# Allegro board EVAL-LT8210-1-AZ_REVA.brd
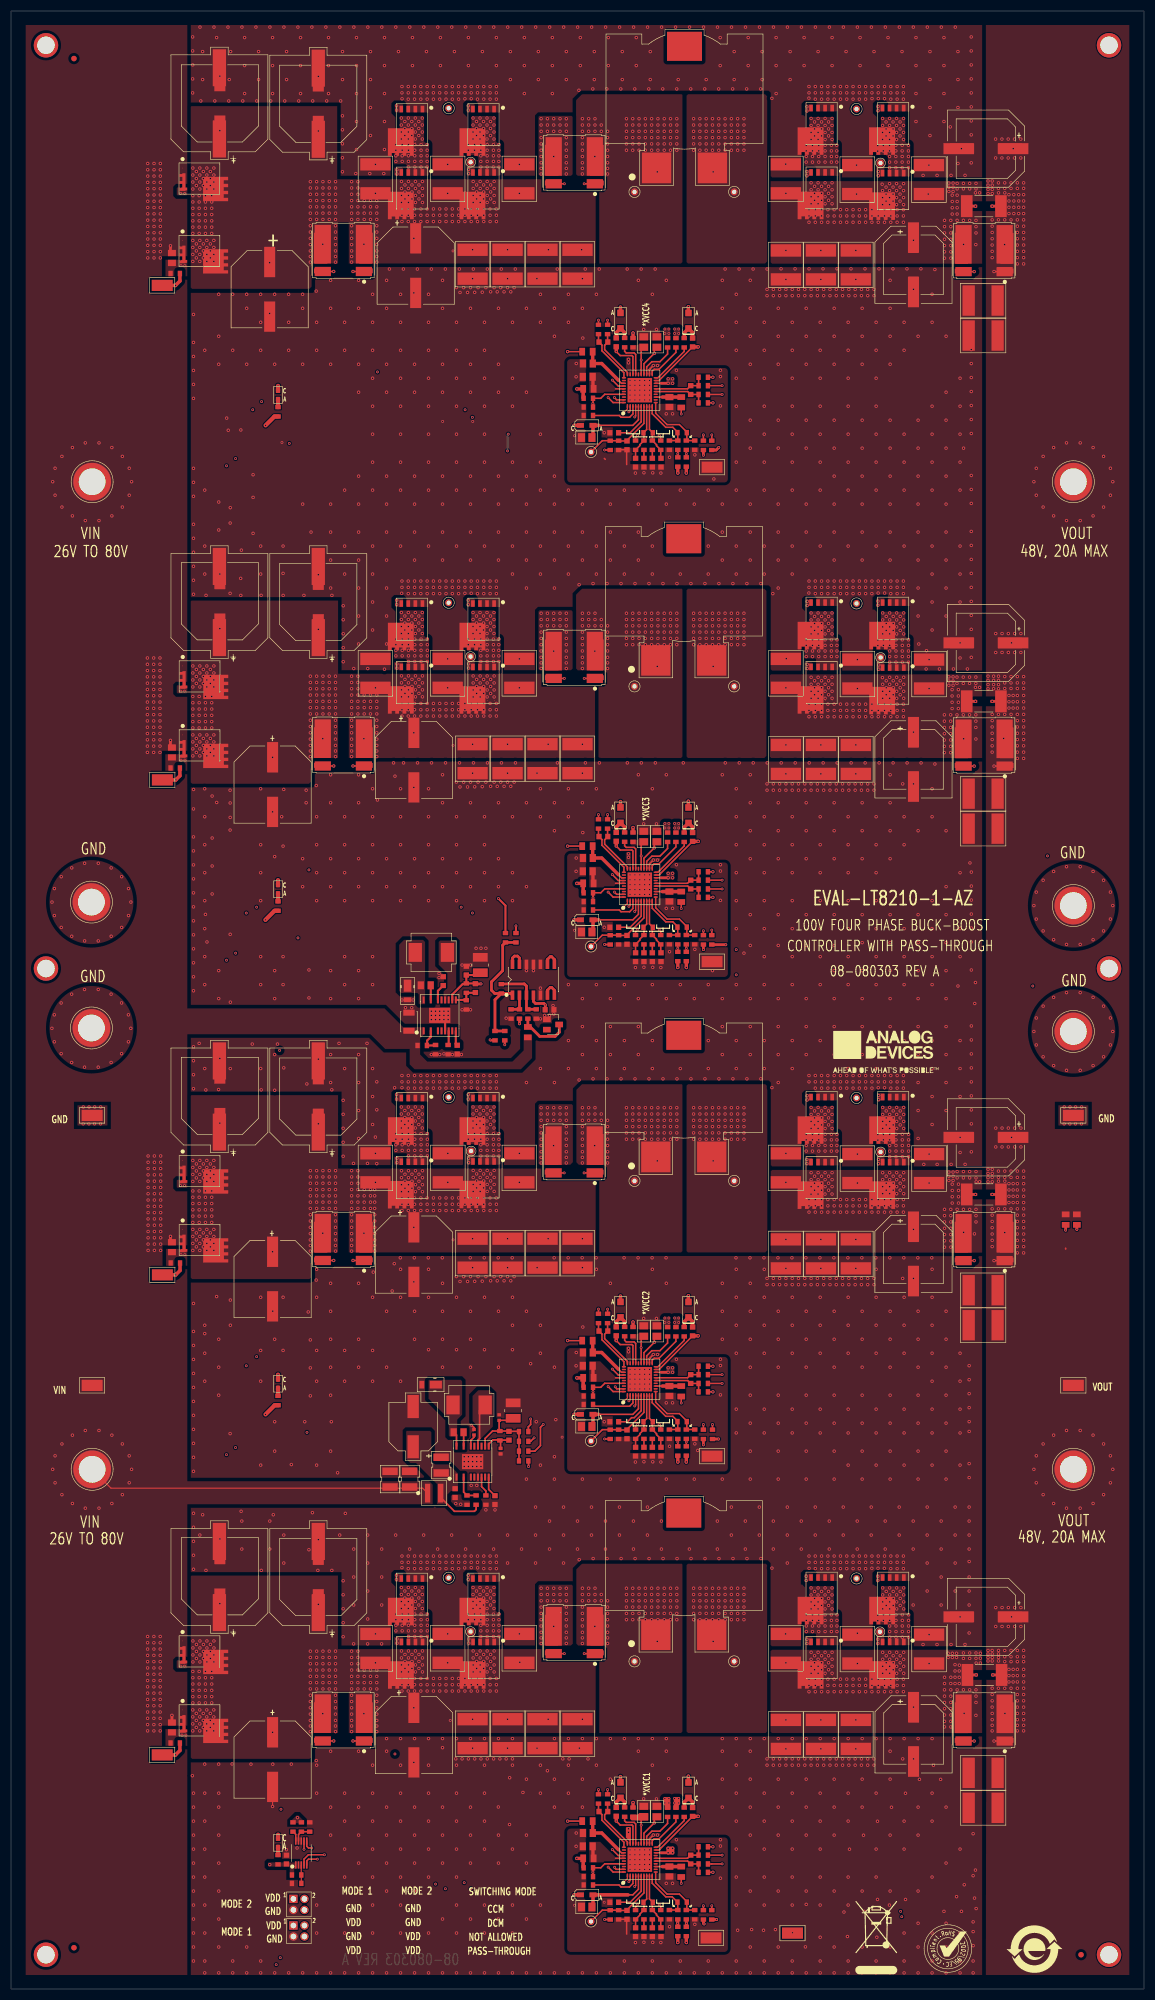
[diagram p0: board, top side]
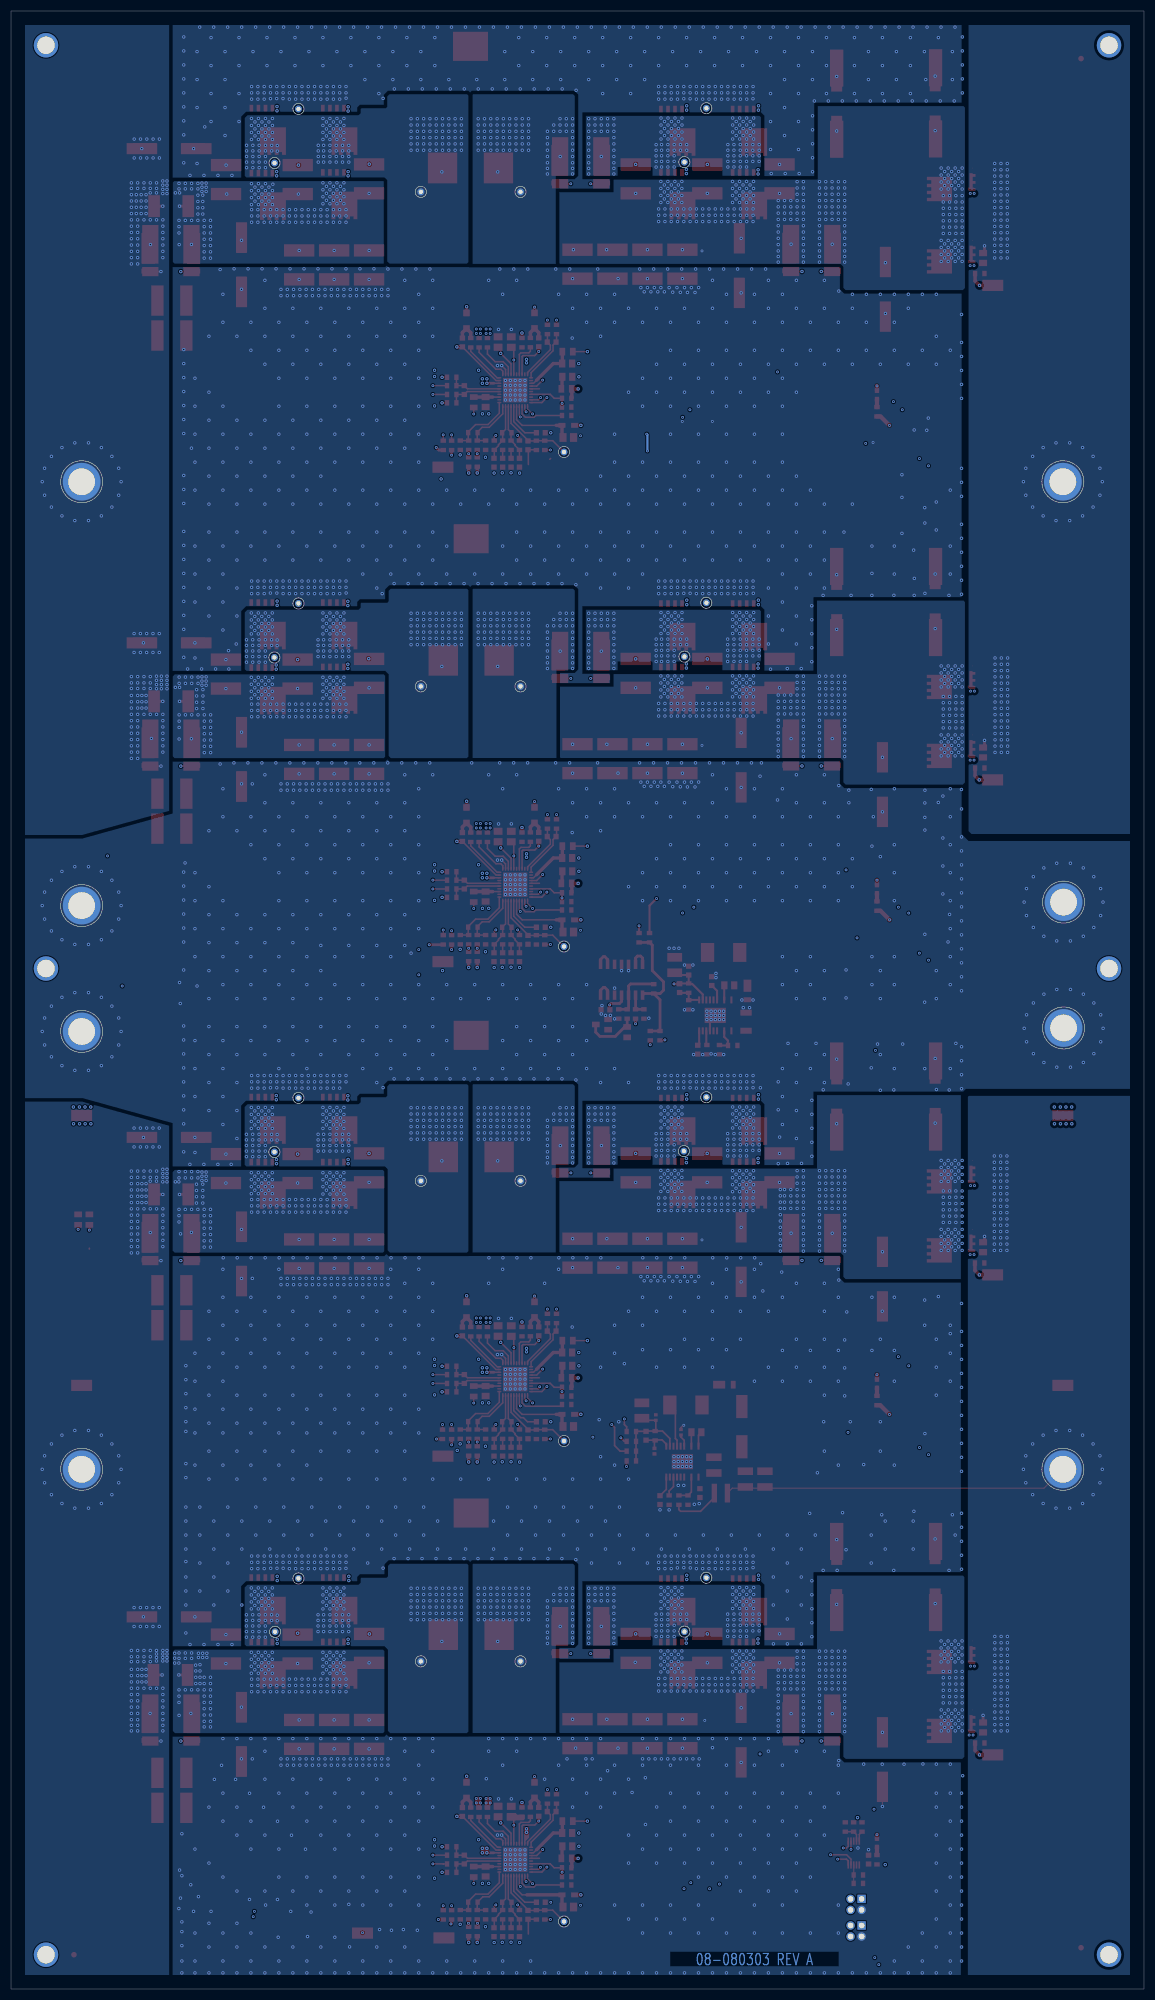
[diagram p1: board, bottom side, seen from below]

Outline 205.74 x 359.16 mm; copper layers: TOP, L2_GND, L3_SIG, L4_GND, L5_VCC, BOTTOM. Coordinates in mm from the lower left corner of the outline.
Outline path: 0,359.16 0,0 205.74,0 205.74,359.16 0,359.16

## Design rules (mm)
constraint set DEFAULT: min track width 0.203

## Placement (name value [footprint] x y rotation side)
C1  1UF  [C0805H55]  29.22 47.49 90 top
C2  68UF  [CPLSMSQ531H551]  47.5 41.66 270 top
C3  68UF  [CPLSMSQ531H551]  55.8 74.8 90 top
C3_1  68UF  [CPLSMSQ673H886]  55.8 74.8 90 top
C4  68UF  [CPLSMSQ531H551]  37.92 74.93 90 top
C4_1  68UF  [CPLSMSQ673H886]  37.85 74.8 90 top
C5  1UF  [C0805H55]  104.72 25.91 0 top
C6  1UF  [C0805H55]  104.75 28.32 0 top
C7  68UF  [CPLSMSQ531H551]  73.15 46.1 270 top
C8  33UF  [CSML236W200H272]  66.18 61.85 270 top
C9  33UF  [CSML236W200H272]  79.3 61.85 270 top
C10  33UF  [CSML236W200H272]  92.3 61.85 270 top
C11  33UF  [CSML236W200H272]  83.82 46.35 90 top
C12  33UF  [CSML236W200H272]  90.17 46.35 90 top
C13  33UF  [CSML236W200H272]  96.52 46.35 90 top
C14  33UF  [CSML236W200H272]  102.87 46.35 90 top
C15  1000pF  [C0603]  107.57 32.22 0 top
C16  33UF  [CSML236W200H272]  140.72 61.85 270 top
C17  33UF  [CSML236W200H272]  153.7 61.72 270 top
C18  33UF  [CSML236W200H272]  166.71 61.72 270 top
C19  33UF  [CSML236W200H272]  140.72 46.23 90 top
C20  33UF  [CSML236W200H272]  147.07 46.23 90 top
C21  33UF  [CSML236W200H272]  153.42 46.23 90 top
C22  100UF  [CPLSMSQ406H500]  163.89 46.23 270 top
C22_1  68UF  [CPLSMSQ531H551]  163.89 46.23 270 top
C23  100UF  [CPLSMSQ406H500]  177.04 67.56 180 top
C23_1  68UF  [CPLSMSQ531H551]  177.04 67.56 180 top
C24  0.1uF  [C0603]  123.42 23.5 270 top
C25  1UF  [C0805H55]  29.22 134.7 90 top
C26  68UF  [CPLSMSQ531H551]  47.5 128.9 270 top
C27  68UF  [CPLSMSQ531H551]  55.8 162.05 90 top
C27_1  68UF  [CPLSMSQ673H886]  55.8 162.05 90 top
C28  68UF  [CPLSMSQ531H551]  37.92 162.18 90 top
C28_1  68UF  [CPLSMSQ673H886]  37.85 162.05 90 top
C29  1UF  [C0805H55]  104.72 113.16 0 top
C30  1UF  [C0805H55]  104.75 115.57 0 top
C31  68UF  [CPLSMSQ531H551]  73.15 133.35 270 top
C32  33UF  [CSML236W200H272]  66.18 149.1 270 top
C33  33UF  [CSML236W200H272]  79.32 149.1 270 top
C34  33UF  [CSML236W200H272]  92.3 149.1 270 top
C35  33UF  [CSML236W200H272]  83.82 133.6 90 top
C36  33UF  [CSML236W200H272]  90.17 133.6 90 top
C37  33UF  [CSML236W200H272]  96.52 133.6 90 top
C38  33UF  [CSML236W200H272]  102.87 133.6 90 top
C39  1000pF  [C0603]  107.57 119.47 0 top
C40  33UF  [CSML236W200H272]  140.72 149.1 270 top
C41  33UF  [CSML236W200H272]  153.7 148.97 270 top
C42  33UF  [CSML236W200H272]  166.71 148.97 270 top
C43  33UF  [CSML236W200H272]  140.72 133.48 90 top
C44  33UF  [CSML236W200H272]  147.07 133.48 90 top
C45  33UF  [CSML236W200H272]  153.42 133.48 90 top
C46  100UF  [CPLSMSQ406H500]  163.88 133.48 270 top
C46_1  68UF  [CPLSMSQ531H551]  163.88 133.48 270 top
C47  100UF  [CPLSMSQ406H500]  177.04 154.63 180 top
C47_1  68UF  [CPLSMSQ531H551]  177.04 154.63 180 top
C48  0.1uF  [C0603]  123.42 110.75 270 top
C49  1UF  [C0805H55]  29.22 224.52 90 top
C50  68UF  [CPLSMSQ531H551]  47.5 218.69 270 top
C51  68UF  [CPLSMSQ531H551]  55.8 251.84 90 top
C51_1  68UF  [CPLSMSQ673H886]  55.8 251.84 90 top
C52  68UF  [CPLSMSQ531H551]  37.92 251.97 90 top
C52_1  68UF  [CPLSMSQ673H886]  37.85 251.84 90 top
C53  1UF  [C0805H55]  104.72 202.95 0 top
C54  1UF  [C0805H55]  104.75 205.36 0 top
C55  68UF  [CPLSMSQ531H551]  73.15 223.14 270 top
C56  33UF  [CSML236W200H272]  66.18 238.89 270 top
C57  33UF  [CSML236W200H272]  79.3 238.89 270 top
C58  33UF  [CSML236W200H272]  92.3 238.89 270 top
C59  33UF  [CSML236W200H272]  83.82 223.39 90 top
C60  33UF  [CSML236W200H272]  90.17 223.39 90 top
C61  33UF  [CSML236W200H272]  96.52 223.39 90 top
C62  33UF  [CSML236W200H272]  102.87 223.39 90 top
C63  1000pF  [C0603]  107.57 209.26 0 top
C64  33UF  [CSML236W200H272]  140.72 238.89 270 top
C65  33UF  [CSML236W200H272]  153.7 238.76 270 top
C66  33UF  [CSML236W200H272]  166.71 238.76 270 top
C67  33UF  [CSML236W200H272]  140.72 223.27 90 top
C68  33UF  [CSML236W200H272]  153.42 223.27 90 top
C69  33UF  [CSML236W200H272]  147.07 223.27 90 top
C70  100UF  [CPLSMSQ406H500]  163.88 223.27 270 top
C70_1  68UF  [CPLSMSQ531H551]  163.88 223.27 270 top
C71  100UF  [CPLSMSQ406H500]  177.04 244.42 180 top
C71_1  68UF  [CPLSMSQ531H551]  177.04 244.42 180 top
C72  0.1uF  [C0603]  123.42 200.54 270 top
C73  1UF  [C0805H55]  29.22 314.31 90 top
C74  68UF  [CPLSMSQ531H551]  46.96 308.62 270 top
C75  68UF  [CPLSMSQ531H551]  55.8 342.33 90 top
C75_1  68UF  [CPLSMSQ673H886]  55.8 342.33 90 top
C76  68UF  [CPLSMSQ531H551]  37.92 342.38 90 top
C76_1  68UF  [CPLSMSQ673H886]  37.85 342.39 90 top
C77  1UF  [C0805H55]  104.72 292.73 0 top
C78  1UF  [C0805H55]  104.75 295.15 0 top
C79  68UF  [CPLSMSQ531H551]  73.48 312.93 270 top
C80  33UF  [CSML236W200H272]  66.18 328.68 270 top
C81  33UF  [CSML236W200H272]  79.3 328.68 270 top
C82  33UF  [CSML236W200H272]  92.3 328.68 270 top
C83  33UF  [CSML236W200H272]  83.82 313.18 90 top
C84  33UF  [CSML236W200H272]  90.17 313.18 90 top
C85  33UF  [CSML236W200H272]  96.52 313.18 90 top
C86  33UF  [CSML236W200H272]  102.87 313.18 90 top
C87  1000pF  [C0603]  107.57 299.04 0 top
C88  33UF  [CSML236W200H272]  140.72 328.68 270 top
C89  33UF  [CSML236W200H272]  153.67 328.55 270 top
C90  33UF  [CSML236W200H272]  166.69 328.55 270 top
C91  33UF  [CSML236W200H272]  140.72 313.05 90 top
C92  33UF  [CSML236W200H272]  147.07 313.05 90 top
C93  33UF  [CSML236W200H272]  153.42 313.05 90 top
C94  100UF  [CPLSMSQ406H500]  163.88 313.08 270 top
C94_1  68UF  [CPLSMSQ531H551]  163.88 313.08 270 top
C95  100UF  [CPLSMSQ406H500]  177.04 334.16 180 top
C95_1  68UF  [CPLSMSQ531H551]  177.04 334.16 180 top
C96  0.1uF  [C0603]  123.42 290.33 270 top
C97  0.1uF  [C0603]  50.01 23.49 90 top
C98  10uF  [CPLSMSQ327H413]  73.02 102.11 90 top
C99  2.2UF  [C1210H110]  72.39 92.58 90 top
C100  2.2UF  [C1210H110]  78.1 95.12 90 top
C101  2.2UF  [C1210H110]  68.83 92.58 90 top
C102  TBD0603  [C0603]  80.64 90.04 90 top
C103  0.1uF  [C0603]  87.88 88.77 270 top
C104  0.1UF  [C0805]  81.28 101.09 0 top
C105  4.7PF  [C0603]  90.42 100.46 270 top
C106  2.2UF  [C0402]  84.07 101.09 90 top
C107  47uF  [C1210-2]  91.19 105.03 90 top
C108  1uF  [C0402]  88.65 103.76 90 top
C109  33UF  [CSML236W200H272]  176.53 32.89 0 top
C110  33UF  [CSML236W200H272]  176.53 39.24 0 top
C111  33UF  [CSML236W200H272]  176.53 217.04 0 top
C112  33UF  [CSML236W200H272]  176.53 210.69 0 top
C113  33UF  [CSML236W200H272]  176.53 306.58 0 top
C114  33UF  [CSML236W200H272]  176.53 300.23 0 top
C115  33UF  [CSML236W200H272]  176.53 126.87 0 top
C116  33UF  [CSML236W200H272]  176.53 120.52 0 top
C117  10UF  [C1210H106]  72.26 175.64 90 top
C118  0.01uF  [C0603]  81.03 170.56 270 top
C119  0.1uF  [C0603]  97.79 177.8 0 top
C120  0.1UF  [C0805]  75.31 182.25 0 top
C121  4.7PF  [C0603]  84.33 181.74 270 top
C122  2.2UF  [C0603]  78.49 183.01 90 top
C123  47uF  [C1210-2]  85.22 185.93 90 top
C124  1uF  [C0603]  82.68 184.91 90 top
CBST1  0.1uF  [C0603]  109.91 32.17 90 top
CBST2  0.1uF  [C0603]  123.77 32.14 270 top
CBST3  0.1uF  [C0603]  109.91 119.42 90 top
CBST4  0.1uF  [C0603]  123.77 119.39 270 top
CBST5  0.1uF  [C0603]  109.91 209.21 90 top
CBST6  0.1uF  [C0603]  123.77 209.18 270 top
CBST7  0.1uF  [C0603]  109.91 298.99 90 top
CBST8  0.1uF  [C0603]  123.77 298.97 270 top
CC1  6800pF  [C0603]  114.93 10.31 90 top
CC2  6800pF  [C0603]  116.46 10.31 90 top
CC3  6800pF  [C0603]  114.94 97.56 90 top
CC4  6800pF  [C0603]  116.46 97.56 90 top
CC5  6800pF  [C0603]  114.93 187.35 90 top
CC6  6800pF  [C0603]  116.46 187.35 90 top
CC7  6800pF  [C0603]  114.93 277.14 90 top
CC8  6800pF  [C0603]  116.46 277.14 90 top
CFOUT1  1UF  [C0805H55]  119.56 21.33 270 top
CFOUT2  1UF  [C0805H55]  119.56 108.58 270 top
CFOUT3  1UF  [C0805H55]  119.56 198.37 270 top
CFOUT4  1UF  [C0805H55]  119.56 288.16 270 top
CGATE1  4.7uF  [C0805H53]  117.28 32.22 90 top
CGATE2  4.7uF  [C0805H53]  117.28 119.47 90 top
CGATE3  4.7uF  [C0805H53]  117.28 209.26 90 top
CGATE4  4.7uF  [C0805H53]  117.28 299.05 90 top
CIMON1  0.01uF  [C0603]  111.86 13.46 270 top
CIMON2  0.01uF  [C0603]  111.86 100.71 270 top
CIMON3  0.01uF  [C0603]  111.86 190.5 270 top
CIMON4  0.01uF  [C0603]  111.86 280.29 270 top
CP1  220pF  [C0603]  113.41 10.31 90 top
CP2  62PF  [C0603]  118.03 10.31 90 top
CP3  220pF  [C0603]  113.41 97.56 90 top
CP4  62PF  [C0603]  118.03 97.56 90 top
CP5  220pF  [C0603]  113.41 187.35 90 top
CP6  62PF  [C0603]  118.03 187.35 90 top
CP7  220pF  [C0603]  113.41 277.14 90 top
CP8  62PF  [C0603]  118.03 277.14 90 top
CSS1  0.22UF  [C0603]  109.54 15.75 0 top
CSS2  0.22UF  [C0603]  109.54 103 0 top
CSS3  0.22UF  [C0603]  109.54 192.79 0 top
CSS4  0.22UF  [C0603]  109.54 282.57 0 top
CVDD1  4.7uF  [C0805H53]  104.55 14.88 0 top
CVDD2  4.7uF  [C0805H53]  104.55 102.13 0 top
CVDD3  4.7uF  [C0805H53]  104.55 191.92 0 top
CVDD4  4.7uF  [C0805H53]  104.55 281.71 0 top
CXVCC1  4.7uF  [C0805H53]  114.9 32.22 270 top
CXVCC2  4.7uF  [C0805H53]  114.9 119.47 270 top
CXVCC3  4.7uF  [C0805H53]  114.9 209.26 270 top
CXVCC4  4.7uF  [C0805H53]  114.9 299.04 270 top
D1  PMEG3010BEA,115  [SOD323]  104.55 17.09 0 top
D2  BZX84-C18V  [SOT23]  98.42 175.13 270 top
D3  PMEG3010BEA,115  [SOD323]  104.55 104.34 0 top
D4  DFLS1100-7  [POWERDI123]  72.01 181.23 270 top
D5  PMEG3010BEA,115  [SOD323]  104.55 194.13 0 top
D7  PMEG3010BEA,115  [SOD323]  104.55 283.92 0 top
D9  DFLS1100-7  [POWERDI123]  76.2 109.73 180 top
DBST1  US1GWF-7  [SOD123F]  110.68 36.1 90 top
DBST2  US1GWF-7  [SOD123F]  123.03 36.09 90 top
DBST3  US1GWF-7  [SOD123F]  110.68 123.35 90 top
DBST4  US1GWF-7  [SOD123F]  123.03 123.34 90 top
DBST5  US1GWF-7  [SOD123F]  110.68 213.14 90 top
DBST6  US1GWF-7  [SOD123F]  123.03 213.13 90 top
DBST7  US1GWF-7  [SOD123F]  110.68 302.93 90 top
DBST8  US1GWF-7  [SOD123F]  123.03 302.92 90 top
DG1  5019  [CNKEY5019]  27.46 42.51 0 top
DG2  5019  [CNKEY5019]  27.48 129.67 0 top
DG3  5019  [CNKEY5019]  27.48 219.54 0 top
DG4  5019  [CNKEY5019]  27.46 309.33 0 top
DS1  HSMC-C197  [LED0603H12]  48.49 26.54 270 top
DS2  HSMC-C197  [LED0603H12]  48.49 109.91 270 top
DS3  HSMC-C197  [LED0603H12]  48.49 199.69 270 top
DS4  HSMC-C197  [LED0603H12]  48.49 289.45 270 top
E1  5019  [CNKEY5019]  14.73 109.6 0 top
E2  5019  [CNKEY5019]  14.73 158.62 0 top
E3  5019  [CNKEY5019]  192.91 158.62 0 top
E4  5019  [CNKEY5019]  192.91 109.6 0 top
GND1  5019  [CNKEY5019]  127.13 9.27 180 top
GND2  5019  [CNKEY5019]  127.31 96.75 180 top
GND3  5019  [CNKEY5019]  127.3 186.54 180 top
GND4  5019  [CNKEY5019]  127.3 276.33 180 top
IMON  5019  [CNKEY5019]  141.91 10.15 180 top
IMON1  TESTPAD  [TPC50D30]  105.32 12.26 270 top
IMON2  TESTPAD  [TPC50D30]  105.32 99.5 270 top
IMON3  TESTPAD  [TPC50D30]  105.32 189.29 270 top
IMON4  TESTPAD  [TPC50D30]  105.32 279.08 270 top
JP1  TMM-102-02-L-D  [CNTHMHDR2X2L157W155H225]  51.28 11.53 270 top
JP2  TMM-102-02-L-D  [CNTHMHDR2X2L157W155H225]  51.28 16.36 270 top
L1  15UH  [LSML1102W764H728]  122.17 75.91 0 top
L1A  TESTPAD  [TPC50D30]  113.22 59.49 0 top
L1B  TESTPAD  [TPC50D30]  131.32 59.49 0 top
L2  15UH  [LSML1102W764H728]  122.17 162.65 0 top
L2A  TESTPAD  [TPC50D30]  113.22 146.74 0 top
L2B  TESTPAD  [TPC50D30]  131.32 146.74 0 top
L3  15UH  [LSML1102W764H728]  122.17 252.82 0 top
L3A  TESTPAD  [TPC50D30]  113.22 236.52 0 top
L3B  TESTPAD  [TPC50D30]  131.32 236.52 0 top
L4  15UH  [LSML1102W764H728]  122.3 342.23 0 top
L4A  TESTPAD  [TPC50D30]  113.22 326.31 0 top
L4B  TESTPAD  [TPC50D30]  131.32 326.31 0 top
L5  2.2uH  [LSMSQ157H83_CC]  76.83 90.04 0 top
L6  22UH  [LSML270W255H118]  83.18 106.05 180 top
L7  22UH  [LSML270W255H118]  76.33 188.21 180 top
MA1  BSC070N10NS3GATMA1  [SON8]  72.81 60.19 180 top
MA2  BSC070N10NS3GATMA1  [SON8]  85.83 60.19 180 top
MA3  BSC070N10NS3GATMA1  [SON8]  72.78 147.38 180 top
MA4  BSC070N10NS3GATMA1  [SON8]  85.8 147.43 180 top
MA5  BSC070N10NS3GATMA1  [SON8]  72.78 237.24 180 top
MA6  BSC070N10NS3GATMA1  [SON8]  85.8 237.22 180 top
MA7  BSC070N10NS3GATMA1  [SON8]  72.78 327.01 180 top
MA8  BSC070N10NS3GATMA1  [SON8]  85.8 327.01 180 top
MB1  BSC070N10NS3GATMA1  [SON8]  72.78 71.7 180 top
MB2  BSC070N10NS3GATMA1  [SON8]  85.8 71.7 180 top
MB3  BSC070N10NS3GATMA1  [SON8]  72.78 158.95 180 top
MB4  BSC070N10NS3GATMA1  [SON8]  85.8 158.95 180 top
MB5  BSC070N10NS3GATMA1  [SON8]  72.78 248.74 180 top
MB6  BSC070N10NS3GATMA1  [SON8]  85.8 248.74 180 top
MB7  BSC070N10NS3GATMA1  [SON8]  72.78 338.53 180 top
MB8  BSC070N10NS3GATMA1  [SON8]  85.8 338.53 180 top
MC1  BSC070N10NS3GATMA1  [SON8]  147.19 71.88 180 top
MC2  BSC070N10NS3GATMA1  [SON8]  160.2 71.88 180 top
MC3  BSC070N10NS3GATMA1  [SON8]  147.19 159.13 180 top
MC4  BSC070N10NS3GATMA1  [SON8]  160.2 159.13 180 top
MC5  BSC070N10NS3GATMA1  [SON8]  147.19 248.92 180 top
MC6  BSC070N10NS3GATMA1  [SON8]  160.2 248.92 180 top
MC7  BSC070N10NS3GATMA1  [SON8]  147.19 338.71 180 top
MC8  BSC070N10NS3GATMA1  [SON8]  160.17 338.71 180 top
MD1  BSC070N10NS3GATMA1  [SON8]  147.19 60.2 180 top
MD2  BSC070N10NS3GATMA1  [SON8]  160.2 60.2 180 top
MD3  BSC070N10NS3GATMA1  [SON8]  147.19 147.32 180 top
MD4  BSC070N10NS3GATMA1  [SON8]  160.2 147.32 180 top
MD5  BSC070N10NS3GATMA1  [SON8]  147.19 237.24 180 top
MD6  BSC070N10NS3GATMA1  [SON8]  160.2 237.11 180 top
MD7  BSC070N10NS3GATMA1  [SON8]  147.19 327.02 180 top
MD8  BSC070N10NS3GATMA1  [SON8]  160.17 326.9 180 top
MDG1  ISC030N10NM6ATMA1  [SON8_FL]  34.23 48.77 270 top
MDG2  ISC030N10NM6ATMA1  [SON8_FL]  34.23 61.29 270 top
MDG3  ISC030N10NM6ATMA1  [SON8_FL]  34.24 136.02 270 top
MDG4  ISC030N10NM6ATMA1  [SON8_FL]  34.24 148.54 270 top
MDG5  ISC030N10NM6ATMA1  [SON8_FL]  34.24 225.81 270 top
MDG6  ISC030N10NM6ATMA1  [SON8_FL]  34.24 238.33 270 top
MDG7  ISC030N10NM6ATMA1  [SON8_FL]  34.21 315.59 270 top
MDG8  ISC030N10NM6ATMA1  [SON8_FL]  34.21 328.74 270 top
NOREF  -  [unnamed]  194.31 6.22 0 top
NOREF#2  -  [#2]  6.35 6.22 0 top
NOREF#3  -  [#2]  64.95 185.93 0 top
NOREF#4  -  [#2]  103.63 383.16 0 top
NOREF#5  -  [#2]  158.89 170.14 0 top
NOREF#6  -  [#2]  0 0 0 top
NOREF#7  -  [#2]  -69.6 -14.22 0 top
NOREF#8  -  [unnamed]  11.43 7.49 0 top
NOREF#9  -  [#2]  205.74 0 0 top
NOREF#10  -  [#2]  -63.5 -28.7 0 top
NOREF#11  -  [#2]  -25.4 -34.54 0 top
NOREF#12  -  [unnamed]  6.35 352.93 0 top
NOREF#13  -  [#2]  195.17 92.13 0 top
NOREF#14  -  [#2]  213.49 315.85 0 top
NOREF#15  -  [#2]  201.61 6.22 0 top
NOREF#16  -  [unnamed]  199.39 352.93 0 top
NOREF#17  -  [#2]  0 0 0 top
NOREF#18  -  [#2]  287.02 133.86 0 top
NOREF#19  -  [#2]  170.13 7.34 0 top
NOREF#20  -  [unnamed]  6.35 6.22 0 top
NOREF#21  -  [#2]  0 359.16 270 top
NOREF#22  -  [#2]  205.74 0 90 top
NOREF#23  -  [#2]  0 0 0 top
NOREF#24  -  [#2]  0 359.16 0 top
NOREF#25  -  [#2]  205.74 359.16 180 top
NOREF#26  -  [#2]  185.85 7.24 0 top
NOREF#27  -  [#2]  6.35 6.22 0 top
NOREF#28  -  [unnamed]  199.39 6.22 0 top
NOREF#29  -  [#2]  166.4 19.56 0 top
NOREF#30  -  [unnamed]  11.43 350.52 0 top
NOREF#31  -  [unnamed]  6.35 185.29 0 top
NOREF#32  -  [unnamed]  199.39 185.29 0 top
NOREF#33  -  [#2]  5.08 -4.06 0 top
NOREF#34  -  [#2]  0 359.16 0 top
NOREF#35  -  [#2]  205.74 0 90 top
P1  KFH-032-10ET  [CNPEMKFH-032]  14.73 273.69 0 top
P2  KFH-032-10ET  [CNPEMKFH-032]  14.73 94.36 0 top
P3  KFH-032-10ET  [CNPEMKFH-032]  14.61 174.5 0 top
P4  KFH-032-10ET  [CNPEMKFH-032]  14.61 197.36 0 top
P5  KFH-032-10ET  [CNPEMKFH-032]  192.91 196.72 0 top
P6  KFH-032-10ET  [CNPEMKFH-032]  192.91 173.86 0 top
P7  KFH-032-10ET  [CNPEMKFH-032]  192.91 273.69 0 top
P8  KFH-032-10ET  [CNPEMKFH-032]  192.91 94.36 0 top
R1  0  [R0603]  29.82 44.67 0 top
R1A1  825K  [R0603]  122.63 13.49 90 top
R1A2  825K  [R0603]  122.63 100.74 90 top
R1A3  825K  [R0603]  122.63 190.53 90 top
R1A4  825K  [R0603]  122.63 280.31 90 top
R1B1  23.7K  [R0603]  124.16 13.49 270 top
R1B2  23.7K  [R0603]  124.16 100.74 270 top
R1B3  23.7K  [R0603]  124.16 190.53 270 top
R1B4  23.7K  [R0603]  124.16 280.31 270 top
R1C1  0  [R0603]  122.63 10.44 270 top
R1C2  0  [R0603]  122.63 97.69 270 top
R1C3  0  [R0603]  122.63 187.48 270 top
R1C4  0  [R0603]  122.63 277.27 270 top
R2  20  [R0805]  104.67 30.48 180 top
R2A1  549K  [R0603]  121.08 13.49 90 top
R2A2  549K  [R0603]  121.08 100.74 90 top
R2A3  549K  [R0603]  121.08 190.53 90 top
R2A4  549K  [R0603]  121.08 280.31 90 top
R2B1  10K  [R0603]  119.56 13.49 90 top
R2B2  10K  [R0603]  119.56 100.74 90 top
R2B3  10K  [R0603]  119.56 190.53 90 top
R2B4  10K  [R0603]  119.56 280.31 90 top
R2C1  0  [R0603]  121.08 10.44 270 top
R2C2  0  [R0603]  121.08 97.69 270 top
R2C3  0  [R0603]  121.08 187.48 270 top
R2C4  0  [R0603]  121.08 277.27 270 top
R3  10  [R0603]  106.68 34.5 270 top
R3C1  TBD0603  [R0603]  121.87 15.77 180 top
R3C2  TBD0603  [R0603]  121.87 103.02 180 top
R3C3  TBD0603  [R0603]  121.87 192.81 180 top
R3C4  TBD0603  [R0603]  121.87 282.6 180 top
R4  10  [R0603]  108.33 34.5 270 top
R5  0  [R0603]  112.95 32.1 270 top
R6  49.9  [R0603]  125.71 24.3 0 top
R7  49.9  [R0603]  125.71 22.7 0 top
R8  499  [R0603]  108.81 13.46 90 top
R9  15K  [R0603]  113.41 13.49 270 top
R10  15K  [R0603]  117.98 13.49 90 top
R11  0  [R0603]  29.84 131.83 0 top
R12  20  [R0805]  104.67 117.73 180 top
R13  10  [R0603]  106.68 121.75 270 top
R14  10  [R0603]  108.33 121.75 270 top
R15  0  [R0603]  112.95 119.35 270 top
R16  49.9  [R0603]  125.71 111.55 0 top
R17  49.9  [R0603]  125.71 109.95 0 top
R18  499  [R0603]  108.81 100.71 90 top
R19  15K  [R0603]  113.41 100.74 270 top
R20  15K  [R0603]  117.98 100.74 90 top
R21  0  [R0603]  29.82 221.7 0 top
R22  20  [R0805]  104.67 207.52 180 top
R23  10  [R0603]  106.68 211.54 270 top
R24  10  [R0603]  108.33 211.54 270 top
R25  0  [R0603]  112.95 209.14 270 top
R26  49.9  [R0603]  125.71 201.34 0 top
R27  49.9  [R0603]  125.71 199.74 0 top
R28  499  [R0603]  108.81 190.5 90 top
R29  15K  [R0603]  113.41 190.53 270 top
R30  15K  [R0603]  117.98 190.53 90 top
R31  0  [R0603]  29.82 311.49 0 top
R32  20  [R0805]  104.67 297.31 180 top
R33  10  [R0603]  106.68 301.33 270 top
R34  10  [R0603]  108.33 301.33 270 top
R35  0  [R0603]  112.95 298.93 270 top
R36  49.9  [R0603]  125.71 291.13 0 top
R37  49.9  [R0603]  125.71 289.53 0 top
R38  499  [R0603]  108.81 280.29 90 top
R39  15K  [R0603]  113.41 280.31 270 top
R40  15K  [R0603]  117.98 280.31 90 top
R41  24.3K  [R0603]  51.21 29.41 270 top
R42  0  [R0603]  52.73 29.41 270 top
R43  0  [R0603]  51.87 20.7 0 top
R44  0  [R0603]  51.87 19.18 180 top
R45  0  [R0603]  54.24 29.41 90 top
R46  1MEG  [R0603]  84.45 88.77 90 top
R47  TBD0603  [R0603]  82.8 88.77 270 top
R48  25.5K  [R0603]  86.23 88.77 270 top
R49  1MEG  [R0603]  88.77 100.46 270 top
R50  86.6K  [R0402]  88.9 97.66 270 top
R51  0  [R0603]  93.09 95.89 0 top
R52  0  [R0603]  93.09 97.66 0 top
R53  0  [R0603]  93.09 99.44 0 top
R54  0  [R0603]  93.09 101.22 0 top
R55  TBD0603  [R0603]  127.25 13.46 270 top
R56  TBD0603  [R0603]  125.73 13.46 270 top
R57  20  [R0805]  193.55 139.7 270 top
R58  20  [R0805]  191.52 139.7 270 top
R59  TBD0603  [R0603]  127.25 190.5 270 top
R60  TBD0603  [R0603]  125.73 190.5 270 top
R61  TBD0603  [R0603]  127.25 280.29 270 top
R62  TBD0603  [R0603]  125.73 280.29 270 top
R63  TBD0603  [R0603]  127.38 100.71 270 top
R64  TBD0603  [R0603]  125.73 100.71 270 top
R65  0.014  [R2512H35]  176.78 57.02 0 top
R66  0.014  [R2512H35]  176.66 233.81 0 top
R67  0.014  [R2512H35]  176.66 323.72 0 top
R68  0.014  [R2512H35]  176.66 144.27 0 top
R69  1MEG  [R0603]  74.68 171.32 0 top
R70  TBD0603  [R0603]  77.09 170.56 270 top
R71  25.5K  [R0603]  79.38 170.56 270 top
R72  191K  [R0805]  93.85 173.74 90 top
R73  30K  [R0603]  93.85 177.04 90 top
R74  10K  [R0603]  95.38 177.04 270 top
R75  121K  [R0603]  92.33 177.04 90 top
R76  30K  [R0603]  90.8 177.04 270 top
R77  221K  [R0603]  89.03 181.61 270 top
R78  1MEG  [R0603]  82.68 181.74 270 top
R79  191K  [R0603]  82.68 178.69 270 top
R80  0  [R0603]  87.88 173.1 270 top
R81  0  [R0603]  91.69 190.88 90 top
R82  0  [R0603]  89.79 190.88 90 top
R83  0  [R0603]  89.66 173.1 270 top
RBG1  0  [R0603]  119.23 32.09 270 top
RBG2  0  [R0603]  120.74 32.09 270 top
RBG3  0  [R0603]  119.23 119.34 270 top
RBG4  0  [R0603]  120.74 119.34 270 top
RBG5  0  [R0603]  119.23 209.13 270 top
RBG6  0  [R0603]  120.74 209.13 270 top
RBG7  0  [R0603]  119.23 298.92 270 top
RBG8  0  [R0603]  120.74 298.92 270 top
RBST1  0  [R0603]  111.43 32.12 270 top
RBST2  0  [R0603]  122.25 32.09 270 top
RBST3  0  [R0603]  111.43 119.37 270 top
RBST4  0  [R0603]  122.25 119.34 270 top
RBST5  0  [R0603]  111.43 209.15 270 top
RBST6  0  [R0603]  122.25 209.13 270 top
RBST7  0  [R0603]  111.43 298.94 270 top
RBST8  0  [R0603]  122.25 298.92 270 top
RC1  30.1K  [R0603]  114.93 13.49 90 top
RC2  30.1K  [R0603]  116.46 13.49 90 top
RC3  46.4K  [R0603]  115.7 15.75 0 top
RC4  30.1K  [R0603]  114.94 100.74 90 top
RC5  30.1K  [R0603]  116.46 100.74 90 top
RC6  TBD0603  [R0603]  115.7 103 0 top
RC7  30.1K  [R0603]  114.93 190.53 90 top
RC8  30.1K  [R0603]  116.46 190.53 90 top
RC9  TBD0603  [R0603]  115.7 192.79 0 top
RC10  30.1K  [R0603]  114.93 280.31 90 top
RC11  30.1K  [R0603]  116.46 280.31 90 top
RC12  TBD0603  [R0603]  115.7 282.57 0 top
REN1  100K  [R0603]  104.84 22.01 180 top
REN2  71.5K  [R0603]  104.84 20.41 0 top
REN3  100K  [R0603]  104.84 109.26 180 top
REN4  71.5K  [R0603]  104.84 107.66 0 top
REN5  100K  [R0603]  104.84 199.05 180 top
REN6  71.5K  [R0603]  104.84 197.45 0 top
REN7  100K  [R0603]  104.84 288.84 180 top
REN8  71.5K  [R0603]  104.84 287.24 0 top
RIMON1  11K  [R0603]  110.34 13.46 270 top
RIMON2  11K  [R0603]  110.34 100.71 270 top
RIMON3  11K  [R0603]  110.34 190.5 270 top
RIMON4  11K  [R0603]  110.34 280.29 270 top
RIN1  20  [R0805]  104.85 23.72 180 top
RIN2  20  [R0805]  104.85 110.97 180 top
RIN3  20  [R0805]  104.85 200.76 180 top
RIN4  20  [R0805]  104.85 290.55 180 top
ROUT1  0  [R0805]  121.71 21.28 270 top
ROUT2  0  [R0805]  121.71 108.53 270 top
ROUT3  0  [R0805]  121.71 198.32 270 top
ROUT4  0  [R0805]  121.71 288.11 270 top
RPWGD1  1.69K  [R0603]  48.49 23.47 270 top
RPWGD2  1.69K  [R0603]  48.49 106.84 270 top
RPWGD3  1.69K  [R0603]  48.49 196.63 270 top
RPWGD4  1.69K  [R0603]  48.49 286.38 270 top
RSNPA1  TBD0603  [R0603]  125.71 25.83 0 top
RSNPA2  TBD0603  [R0603]  125.71 113.08 0 top
RSNPA3  TBD0603  [R0603]  125.71 202.86 0 top
RSNPA4  TBD0603  [R0603]  125.71 292.65 0 top
RSNPB1  TBD0603  [R0603]  125.71 21.18 0 top
RSNPB2  TBD0603  [R0603]  125.71 108.43 0 top
RSNPB3  TBD0603  [R0603]  125.71 198.22 0 top
RSNPB4  TBD0603  [R0603]  125.71 288.01 0 top
RSNS1  0.003  [R3637]  102.29 64.71 180 top
RSNS1_1  0.005  [R4026]  102.29 64.27 180 top
RSNS2  0.002  [R3637]  176.71 48.83 180 top
RSNS2_1  0.005  [R4026]  176.71 48.37 180 top
RSNS3  0.001  [R3637]  60.35 48.84 180 top
RSNS3_1  0.005  [R4026]  60.35 48.39 180 top
RSNS4  0.003  [R3637]  102.26 151.99 180 top
RSNS4_1  0.005  [R4026]  102.26 151.56 180 top
RSNS5  0.002  [R3637]  176.71 136.07 180 top
RSNS5_1  0.005  [R4026]  176.71 135.61 180 top
RSNS6  0.001  [R3637]  60.35 136.09 180 top
RSNS6_1  0.005  [R4026]  60.35 135.64 180 top
RSNS7  0.003  [R3637]  102.29 241.78 180 top
RSNS7_1  0.005  [R4026]  102.29 241.35 180 top
RSNS8  0.002  [R3637]  176.71 225.86 180 top
RSNS8_1  0.005  [R4026]  176.71 225.4 180 top
RSNS9  0.001  [R3637]  60.35 225.88 180 top
RSNS9_1  0.005  [R4026]  60.35 225.42 180 top
RSNS10  0.003  [R3637]  102.29 331.6 180 top
RSNS10_1  0.005  [R4026]  102.29 331.16 180 top
RSNS11  0.002  [R3637]  176.71 315.65 180 top
RSNS11_1  0.005  [R4026]  176.72 315.18 180 top
RSNS12  0.001  [R3637]  60.35 315.67 180 top
RSNS12_1  0.005  [R4026]  60.35 315.21 180 top
RT1  39.2K  [R0603]  104.84 18.88 0 top
RT2  39.2K  [R0603]  104.84 106.13 0 top
RT3  39.2K  [R0603]  104.84 195.92 0 top
RT4  39.2K  [R0603]  104.84 285.71 0 top
RXVCC1  0  [R0603]  114.9 32.22 270 top
RXVCC2  0  [R0603]  114.9 119.47 270 top
RXVCC3  0  [R0603]  114.9 209.26 270 top
RXVCC4  0  [R0603]  114.9 299.04 270 top
TPA1  TESTPAD  [TPC50D30]  83.45 64.9 0 top
TPA2  TESTPAD  [TPC50D30]  83.55 152.15 0 top
TPA3  TESTPAD  [TPC50D30]  83.45 241.93 0 top
TPA4  TESTPAD  [TPC50D30]  83.46 331.72 0 top
TPB1  TESTPAD  [TPC50D30]  79.48 74.68 270 top
TPB2  TESTPAD  [TPC50D30]  79.48 161.92 270 top
TPB3  TESTPAD  [TPC50D30]  79.48 251.71 270 top
TPB4  TESTPAD  [TPC50D30]  79.48 341.5 270 top
TPC1  TESTPAD  [TPC50D30]  153.54 74.55 270 top
TPC2  TESTPAD  [TPC50D30]  153.54 161.8 270 top
TPC3  TESTPAD  [TPC50D30]  153.54 251.59 270 top
TPC4  TESTPAD  [TPC50D30]  153.54 341.38 270 top
TPD1  TESTPAD  [TPC50D30]  157.78 64.86 0 top
TPD2  TESTPAD  [TPC50D30]  157.91 151.98 0 top
TPD3  TESTPAD  [TPC50D30]  157.91 241.77 0 top
TPD4  TESTPAD  [TPC50D30]  157.89 331.56 0 top
U1  LT8210AUJ-1#PBF  [QFN40_6X6_PAD4_42X4_42_05-08-1728]  114.18 23.48 0 top
U2  LT8210AUJ-1#PBF  [QFN40_6X6_PAD4_42X4_42_05-08-1728]  114.19 110.73 0 top
U3  LT8210AUJ-1#PBF  [QFN40_6X6_PAD4_42X4_42_05-08-1728]  114.18 200.52 0 top
U4  LT8210AUJ-1#PBF  [QFN40_6X6_PAD4_42X4_42_05-08-1728]  114.18 290.31 0 top
U5  LTC6902CMS#PBF  [RM10]  52.7 24.69 0 top
U6  LT8631HFE#PBF  [TSSOP20_16P_PAD3_86X2_74_05-08-1924]  83.82 95.76 0 top
U7  LT8631HFE#PBF  [TSSOP20_16P_PAD3_86X2_74_05-08-1924]  77.85 176.78 0 top
U8  LTC2052CS#PBF  [SO14-2]  94.87 183.26 0 top

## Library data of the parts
C1 C5 C6 C25 C29 C30 C49 C53 C54 C73 C77 C78 CFOUT1-CFOUT4 = CAP: User Part Number: UPN; Tolerance: 10; alternate symbols: (C0805H55); part number: CAP_SM-1UF,100V,10,E048499,C0805H55; tolerance: 10
C2-C4 C7 C22_1 C23_1 C26-C28 C31 C46_1 C47_1 C50-C52 C55 C70_1 C71_1 C74-C76 C79 C94_1 C95_1 = CAPP: Tolerance: 20; User Part Number: UPN; alternate symbols: (CPLSMSQ531H551); part number: CAPP_SM-68UF,100V,20,E042912,CPLSMSQ531H551; tolerance: 20
C3_1 C4_1 C27_1 C28_1 C51_1 C52_1 C75_1 C76_1 = CAPP: User Part Number: UPN; Tolerance: 20; alternate symbols: (CPLSMSQ673H886); part number: CAPP_SM-68UF,160V,20,E068852,CPLSMSQ673H886; tolerance: 20
C8-C14 C16-C21 C32-C38 C40-C45 C56-C62 C64-C69 C80-C86 C88-C93 C109-C116 = CAP: User Part Number: UPN; Tolerance: 22; alternate symbols: (CSML236W200H272); part number: CAP_SM-33UF,100V,22,E043544,CSML236W200H272; tolerance: 22
C15 C39 C63 C87 = CAP: User Part Number: UPN; Tolerance: 5; alternate symbols: (C0603); part number: CAP_SM-1000PF,50V,5,E042961,C0603; tolerance: 5
C22 C23 C46 C47 C70 C71 C94 C95 = CAPP: Tolerance: 20; User Part Number: UPN; alternate symbols: (CPLSMSQ406H500); part number: CAPP_SM-100UF,63V,20,E059683,CPLSMSQ406H500; tolerance: 20
C24 C48 C72 C96 = CAP: User Part Number: UPN; Tolerance: 10; alternate symbols: (C0603); part number: CAP_SM-0.1UF,16V,10,E022365,C0603; tolerance: 10
C97 = CAP: User Part Number: UPN; Tolerance: 10; alternate symbols: (C0603); part number: CAP_SM-0.1UF,100V,10,E024908,C0603; tolerance: 10
C98 = CAPP: User Part Number: UPN; Tolerance: 20; alternate symbols: (CPLSMSQ327H413); part number: CAPP_SM-10UF,100V,20,E044889,CPLSMSQ327H413; tolerance: 20
C99-C101 = CAP: Tolerance: 10; User Part Number: UPN; alternate symbols: (C1210H110); part number: CAP_SM-2.2UF,100V,10,E068090,C1210H110; tolerance: 10
C102 = CAP: User Part Number: UPN; alternate symbols: (C0603); part number: CAP_SM-TBD0603,TBD0603,TBD0603,E000382,C0603
C103 CBST1-CBST8 = CAP: User Part Number: UPN; Tolerance: 10; alternate symbols: (C0603); part number: CAP_SM-0.1UF,100V,10,E042962,C0603; tolerance: 10
C104 C120 = CAP: User Part Number: UPN; Tolerance: 10; alternate symbols: (C0805); part number: CAP_SM-0.1UF,16V,10,E062930,C0805; tolerance: 10
C105 C121 = CAP: User Part Number: UPN; Tolerance: 0.25pF; alternate symbols: (C0603); part number: CAP_SM-4.7PF,50V,0.25PF,E044245,C0603; tolerance: 0.25pF
C106 = CAP: User Part Number: UPN; Tolerance: 10; alternate symbols: (C0402); part number: CAP_SM-2.2UF,10V,10,E055500,C0402; tolerance: 10
C107 C123 = CAP: Tolerance: 10; User Part Number: UPN; alternate symbols: (C1210-2); part number: CAP_SM-47UF,10V,10,E011546,C1210-2; tolerance: 10
C108 = CAP: User Part Number: UPN; Tolerance: 10; alternate symbols: (C0402); part number: CAP_SM-1UF,10V,10,E035952,C0402; tolerance: 10
C117 = CAP: Tolerance: 10; User Part Number: UPN; alternate symbols: (C1210H106); part number: CAP_SM-10UF,100V,10,E044329,C1210H106; tolerance: 10
C118 = CAP: User Part Number: UPN; Tolerance: 5; alternate symbols: (C0603); part number: CAP_SM-0.01UF,100V,5,E038280,C0603; tolerance: 5
C119 = CAP: User Part Number: UPN; Tolerance: 10; alternate symbols: (C0603); part number: CAP_SM-0.1UF,50V,10,E011865,C0603; tolerance: 10
C122 = CAP: User Part Number: UPN; Tolerance: 10; alternate symbols: (C0603); part number: CAP_SM-2.2UF,10V,10,E066995,C0603; tolerance: 10
C124 = CAP: User Part Number: UPN; Tolerance: 10; alternate symbols: (C0603); part number: CAP_SM-1UF,10V,10,E024444,C0603; tolerance: 10
CC1-CC8 = CAP: User Part Number: UPN; Tolerance: 10; alternate symbols: (C0603); part number: CAP_SM-6800PF,50V,10,E007966,C0603; tolerance: 10
CGATE1-CGATE4 CVDD1-CVDD4 CXVCC1-CXVCC4 = CAP: Tolerance: 10; User Part Number: UPN; alternate symbols: (C0805H53); part number: CAP_SM-4.7UF,50V,10,E028468,C0805H53; tolerance: 10
CIMON1-CIMON4 = CAP: User Part Number: UPN; Tolerance: 10; alternate symbols: (C0603); part number: CAP_SM-0.01UF,50V,10,E038603,C0603; tolerance: 10
CP1 CP3 CP5 CP7 = CAP: User Part Number: UPN; Tolerance: 5; alternate symbols: (C0603); part number: CAP_SM-220PF,50V,5,E042972,C0603; tolerance: 5
CP2 CP4 CP6 CP8 = CAP: User Part Number: UPN; Tolerance: 5; alternate symbols: (C0603); part number: CAP_SM-62PF,50V,5,E046982,C0603; tolerance: 5
CSS1-CSS4 = CAP: User Part Number: UPN; Tolerance: 10; alternate symbols: (C0603); part number: CAP_SM-0.22UF,100V,10,E061685,C0603; tolerance: 10
D1 D3 D5 D7 = DIOSCHOTTKY: Tolerance: N/A; User Part Number: UPN; alternate symbols: (SOD323); part number: DIOSCHOTTKY_SM-PMEG3010BEA,115,30V,N/A,E014012,SOD323; tolerance: N/A
D2 = DIOMMBZ5221: User Part Number: UPN; Tolerance: 5; alternate symbols: (SOT23); part number: DIOMMBZ5221_SM-BZX84-C18V,18V,5,E001202,SOT23; tolerance: 5
D4 D9 = DIOSCHOTTKY: User Part Number: UPN; Tolerance: N/A; alternate symbols: (POWERDI123); part number: DIOSCHOTTKY_SM-DFLS1100-7,100V,N/A,E029142,POWERDI123; tolerance: N/A
DBST1-DBST8 = DIO: Tolerance: N/A; User Part Number: UPN; alternate symbols: (SOD123F); part number: DIO_SM-US1GWF-7,400V,N/A,E042975,SOD123F; tolerance: N/A
DG1-DG4 E1-E4 GND1-GND4 IMON = CNTP1P: User Part Number: UPN; Tolerance: N/A; alternate symbols: (CNKEY5019); part number: CNTP1P_SM-5019,E021431,CNKEY5019; tolerance: N/A
DS1-DS4 = DIOLED: User Part Number: UPN; Tolerance: N/A; alternate symbols: (LED0603H12); part number: DIOLED_SM-HSMC-C197,1.9V,N/A,E060252,LED0603H12; tolerance: N/A
IMON1-IMON4 L1A L1B L2A L2B L3A L3B L4A L4B TPA1-TPA4 TPB1-TPB4 TPC1-TPC4 TPD1-TPD4 = NCTESTPAD: Tolerance: N/A; User Part Number: UPN; alternate symbols: (TPC50D30); part number: NCTESTPAD_TH-TESTPAD,E007450,TPC50D30; tolerance: N/A
JP1 JP2 = CN4P_JMPRSHRT: User Part Number: UPN; Tolerance: N/A; alternate symbols: (CNTHMHDR2X2L157W155H225); part number: CN4P_JMPRSHRT_TH-TMM-102-02-L-D,E043052,CNTHMHDR2X2L157W155H225; tolerance: N/A
L1-L4 = IND: User Part Number: UPN; Tolerance: 15; alternate symbols: (LSML1102W764H728); part number: IND_SM-15UH,15,E061087,LSML1102W764H728; tolerance: 15
L5 = IND: User Part Number: UPN; Tolerance: 20; alternate symbols: (LSMSQ157H83_CC); part number: IND_SM-2.2UH,20,E016651,LSMSQ157H83_CC; tolerance: 20
L6 L7 = IND: User Part Number: UPN; Tolerance: 20; alternate symbols: (LSML270W255H118); part number: IND_SM-22UH,20,E047705,LSML270W255H118; tolerance: 20
MA1-MA8 MB1-MB8 MC1-MC8 MD1-MD8 = TRANNMOSFET8P: Tolerance: N/A; User Part Number: UPN; alternate symbols: (SON8); part number: TRANNMOSFET8P_SM-BSC070N10NS3GATMA1,E059896,SON8; tolerance: N/A
MDG1-MDG8 = TRANNMOSFET_V15: Tolerance: N/A; User Part Number: UPN; alternate symbols: (SON8_FL); part number: TRANNMOSFET_V15_SM-ISC030N10NM6ATMA1,E063963,SON8_FL; tolerance: N/A
P1-P8 = CN1P: User Part Number: UPN; Tolerance: N/A; alternate symbols: (CNPEMKFH-032); part number: CN1P_TH-KFH-032-10ET,E039893,CNPEMKFH-032; tolerance: N/A
R1 R1C1-R1C4 R2C1-R2C4 R5 R11 R15 R21 R25 R31 R35 R42-R45 RBG1-RBG8 RBST1-RBST8 RXVCC1-RXVCC4 = RES: User Part Number: UPN; Tolerance: JUMPER; alternate symbols: (R0603); part number: RES_SM-0,E007502,1/10W,JUMPER,R0603; tolerance: JUMPER
R1A1-R1A4 = RES: User Part Number: UPN; Tolerance: 1; alternate symbols: (R0603); part number: RES_SM-825K,E028541,1/10W,1,R0603; tolerance: 1
R1B1-R1B4 = RES: User Part Number: UPN; Tolerance: 1; alternate symbols: (R0603); part number: RES_SM-23.7K,E042867,1/10W,1,R0603; tolerance: 1
R2 R12 R22 R32 R57 R58 RIN1-RIN4 = RES: User Part Number: UPN; Tolerance: 1; alternate symbols: (R0805); part number: RES_SM-20,E003563,1/8W,1,R0805; tolerance: 1
R2A1-R2A4 = RES: User Part Number: UPN; Tolerance: 1; alternate symbols: (R0603); part number: RES_SM-549K,E064436,1/10W,1,R0603; tolerance: 1
R2B1-R2B4 = RES: User Part Number: UPN; Tolerance: 1; alternate symbols: (R0603); part number: RES_SM-10K,E058983,1/10W,1,R0603; tolerance: 1
R3 R4 R13 R14 R23 R24 R33 R34 = RES: User Part Number: UPN; Tolerance: 1; alternate symbols: (R0603); part number: RES_SM-10,E003666,1/10W,1,R0603; tolerance: 1
R3C1-R3C4 R47 R55 R56 R59-R64 R70 RC6 RC9 RC12 RSNPA1-RSNPA4 RSNPB1-RSNPB4 = RES: User Part Number: UPN; alternate symbols: (R0603); part number: RES_SM-TBD0603,E004050,TBD0603,TBD0603,R0603
R6 R7 R16 R17 R26 R27 R36 R37 = RES: User Part Number: UPN; Tolerance: 1; alternate symbols: (R0603); part number: RES_SM-49.9,E003673,1/10W,1,R0603; tolerance: 1
R8 R18 R28 R38 = RES: User Part Number: UPN; Tolerance: 1; alternate symbols: (R0603); part number: RES_SM-499,E003667,1/10W,1,R0603; tolerance: 1
R9 R10 R19 R20 R29 R30 R39 R40 = RES: User Part Number: UPN; Tolerance: 1; alternate symbols: (R0603); part number: RES_SM-15K,E026585,1/10W,1,R0603; tolerance: 1
R41 = RES: User Part Number: UPN; Tolerance: 1; alternate symbols: (R0603); part number: RES_SM-24.3K,E013392,1/10W,1,R0603; tolerance: 1
R46 R49 R69 R78 = RES: User Part Number: UPN; Tolerance: 1; alternate symbols: (R0603); part number: RES_SM-1MEG,E030873,1/10W,1,R0603; tolerance: 1
R48 R71 = RES: User Part Number: UPN; Tolerance: 1; alternate symbols: (R0603); part number: RES_SM-25.5K,E011039,1/10W,1,R0603; tolerance: 1
R50 = RES: User Part Number: UPN; Tolerance: 1; alternate symbols: (R0402); part number: RES_SM-86.6K,E025011,1/10W,1,R0402; tolerance: 1
R51-R54 R80-R83 = RES: User Part Number: UPN; Tolerance: JUMPER; alternate symbols: (R0603); part number: RES_SM-0,E006826,1/10W,JUMPER,R0603; tolerance: JUMPER
R65-R68 = RES: User Part Number: UPN; Tolerance: 1; alternate symbols: (R2512H35); part number: RES_SM-0.014,E067932,2W,1,R2512H35; tolerance: 1
R72 = RES: User Part Number: UPN; Tolerance: 1; alternate symbols: (R0805); part number: RES_SM-191K,E067952,1/8W,1,R0805; tolerance: 1
R73 R76 = RES: User Part Number: UPN; Tolerance: 5; alternate symbols: (R0603); part number: RES_SM-30K,E042745,1/10W,5,R0603; tolerance: 5
R74 = RES: User Part Number: UPN; Tolerance: 1; alternate symbols: (R0603); part number: RES_SM-10K,E003671,1/10W,1,R0603; tolerance: 1
R75 = RES: User Part Number: UPN; Tolerance: 1; alternate symbols: (R0603); part number: RES_SM-121K,E028772,1/10W,1,R0603; tolerance: 1
R77 = RES: User Part Number: UPN; Tolerance: 1; alternate symbols: (R0603); part number: RES_SM-221K,E044313,1/10W,1,R0603; tolerance: 1
R79 = RES: User Part Number: UPN; Tolerance: 1; alternate symbols: (R0603); part number: RES_SM-191K,E018406,1/10W,1,R0603; tolerance: 1
RC1 RC2 RC4 RC5 RC7 RC8 RC10 RC11 = RES: User Part Number: UPN; Tolerance: 1; alternate symbols: (R0603); part number: RES_SM-30.1K,E011129,1/10W,1,R0603; tolerance: 1
RC3 = RES: User Part Number: UPN; Tolerance: 0.1; alternate symbols: (R0603); part number: RES_SM-46.4K,E024282,1/10W,0.1,R0603; tolerance: 0.1
REN1 REN3 REN5 REN7 = RES: User Part Number: UPN; Tolerance: 1; alternate symbols: (R0603); part number: RES_SM-100K,E030871,1/10W,1,R0603; tolerance: 1
REN2 REN4 REN6 REN8 = RES: User Part Number: UPN; Tolerance: 0.1; alternate symbols: (R0603); part number: RES_SM-71.5K,E024280,1/10W,0.1,R0603; tolerance: 0.1
RIMON1-RIMON4 = RES: User Part Number: UPN; Tolerance: 0.1; alternate symbols: (R0603); part number: RES_SM-11K,E021508,1/10W,0.1,R0603; tolerance: 0.1
ROUT1-ROUT4 = RES: User Part Number: UPN; Tolerance: JUMPER; alternate symbols: (R0805); part number: RES_SM-0,E030875,1/8W,JUMPER,R0805; tolerance: JUMPER
RPWGD1-RPWGD4 = RES: User Part Number: UPN; Tolerance: 1; alternate symbols: (R0603); part number: RES_SM-1.69K,E044022,1/10W,1,R0603; tolerance: 1
RSNS1 RSNS4 RSNS7 RSNS10 = RES4PKEL: Tolerance: 1; User Part Number: UPN; alternate symbols: (R3637); part number: RES4PKEL_SM-0.003,E067217,3W,1,R3637; tolerance: 1
RSNS1_1 RSNS2_1 RSNS3_1 RSNS4_1 RSNS5_1 RSNS6_1 RSNS7_1 RSNS8_1 RSNS9_1 RSNS10_1 RSNS11_1 RSNS12_1 = RES4PKEL: User Part Number: UPN; Tolerance: 1; alternate symbols: (R4026); part number: RES4PKEL_SM-0.005,E043663,3W,1,R4026; tolerance: 1
RSNS2 RSNS5 RSNS8 RSNS11 = RES4PKEL: Tolerance: 1; User Part Number: UPN; alternate symbols: (R3637); part number: RES4PKEL_SM-0.002,E046287,3,1,R3637; tolerance: 1
RSNS3 RSNS6 RSNS9 RSNS12 = RES4PKEL: Tolerance: 1; User Part Number: UPN; alternate symbols: (R3637); part number: RES4PKEL_SM-0.001,E043780,3W,1,R3637; tolerance: 1
RT1-RT4 = RES: User Part Number: UPN; Tolerance: 1; alternate symbols: (R0603); part number: RES_SM-39.2K,E025112,1/10W,1,R0603; tolerance: 1
U1-U4 = ADLT8210_1: Tolerance: N/A; User Part Number: UPN; alternate symbols: (QFN40_6X6_PAD4_42X4_42_05-08-1728); part number: ADLT8210_1_SM-LT8210AUJ-1#PBF,E042637,QFN40_6X6_PAD4_42X4_42_05-08-1728; tolerance: N/A
U5 = ADLTC6902: Tolerance: N/A; User Part Number: UPN; alternate symbols: (RM10); part number: ADLTC6902_SM-LTC6902CMS#PBF,E035295,RM10; tolerance: N/A
U6 U7 = ADLT8631: Tolerance: N/A; User Part Number: UPN; alternate symbols: (TSSOP20_16P_PAD3_86X2_74_05-08-1924); part number: ADLT8631_SM-LT8631HFE#PBF,E044227,TSSOP20_16P_PAD3_86X2_74_05-08-1924; tolerance: N/A
U8 = ADLTC2052X: Tolerance: N/A; User Part Number: UPN; alternate symbols: (SO14-2); part number: ADLTC2052X_SM-LTC2052CS#PBF,E052913,SO14-2; tolerance: N/A

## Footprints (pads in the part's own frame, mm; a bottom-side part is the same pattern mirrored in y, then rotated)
C0402
  rect 0.584x0.66 smd: 1(-0.5,0) 2(0.5,0)
C0603
  rect 0.94x0.991 smd: 1(-0.8,0) 2(0.8,0)
C0805
  rect 1.143x1.448 smd: 1(-0.9,0) 2(0.9,0)
C0805H53
  rect 1.295x1.6 smd: 1(-0.953,0) 2(0.953,0)
C0805H55
  rect 1.143x1.448 smd: 1(-0.9,0) 2(0.9,0)
C1210-2
  rect 1.575x2.692 smd: 1(-1.397,0) 2(1.397,0)
C1210H106
  rect 1.092x2.057 smd: 1(-1.646,0) 2(1.646,0)
C1210H110
  rect 1.372x2.794 smd: 1(-1.431,0) 2(1.431,0)
CNKEY5019
  rect 3.81x2.032 smd: 1(0,0)
CNPEMKFH-032
  round 6.858 hole 4.851: 1(0,0)
CNTHMHDR2X2L157W155H225
  rect 1.524x1.524 hole 1.016: 1(0,0)
  round 1.524 hole 1.016: 2(0,2) 3(2,0) 4(2,2)
CPLSMSQ327H413
  rect 4.191x2.057 smd: N(3.65,0) P(-3.65,0)
CPLSMSQ406H500
  rect 4.394x1.905 smd: N(4.347,0) P(-4.347,0)
CPLSMSQ531H551
  rect 5.512x2.007 smd: N(4.956,0) P(-4.956,0)
CPLSMSQ673H886
  rect 6.731x2.413 smd: N(6.46,0) P(-6.46,0)
CSML236W200H272
  rect 2.235x5.512 smd: 1(-2.628,0) 2(2.628,0)
LED0603H12
  rect 0.787x0.787 smd: A(0.744,0) C(-0.744,0)
LSML270W255H118
  rect 2.413x3.429 smd: 1(-2.921,0) 2(2.921,0)
LSML1102W764H728
  rect 6.35x5.283 smd: (0,10.514)
  rect 5.334x5.588 smd: 1(-5.075,-11.56) 2(5.075,-11.56)
LSMSQ157H83_CC
  rect 0.965x3.404 smd: 1(-1.185,0) 2(1.185,0)
POWERDI123
  rect 0.889x1.397 smd: A(1.606,0)
  rect 2.21x1.397 smd: C(-0.945,0)
QFN40_6X6_PAD4_42X4_42_05-08-1728
  oval 0.279x0.762 smd: 1(-2.25,-2.886) 2(-1.75,-2.886) 3(-1.25,-2.886) 4(-0.75,-2.886) 5(-0.25,-2.886) 6(0.25,-2.886) 7(0.75,-2.886) 8(1.25,-2.886) 9(1.75,-2.886) 10(2.25,-2.886) 21(2.25,2.886) 22(1.75,2.886) 23(1.25,2.886) 24(0.75,2.886) 25(0.25,2.886) 26(-0.25,2.886) 27(-0.75,2.886) 28(-1.25,2.886) 29(-1.75,2.886) 30(-2.25,2.886)
  oval 0.762x0.279 smd: 11(2.886,-2.25) 12(2.886,-1.75) 13(2.886,-1.25) 14(2.886,-0.75) 15(2.886,-0.25) 16(2.886,0.25) 17(2.886,0.75) 18(2.886,1.25) 19(2.886,1.75) 20(2.886,2.25) 31(-2.886,2.25) 32(-2.886,1.75) 33(-2.886,1.25) 34(-2.886,0.75) 35(-2.886,0.25) 36(-2.886,-0.25) 37(-2.886,-0.75) 38(-2.886,-1.25) 39(-2.886,-1.75) 40(-2.886,-2.25)
  rect 4.42x4.42 smd: 41(0,0)
R0402
  rect 0.635x0.737 smd: 1(-0.5,0) 2(0.5,0)
R0603
  rect 0.787x0.991 smd: 1(-0.85,0) 2(0.85,0)
R0805
  rect 1.041x1.397 smd: 1(-0.95,0) 2(0.95,0)
R2512H35
  rect 2.108x3.988 smd: 1(-3.104,0) 2(3.104,0)
R3637
  rect 2.946x1.676 smd: 1(-3.734,3.81) 3(3.734,3.81)
  rect 2.946x7.01 smd: 2(-3.734,-1.143) 4(3.734,-1.143)
R4026
  rect 2.438x0.889 smd: 1(-4.115,3.239) 3(4.115,3.239)
  rect 2.438x5.588 smd: 2(-4.115,-0.889) 4(4.115,-0.889)
RM10
  rect 0.305x1.321 smd: 1(-1,-2.171) 2(-0.5,-2.171) 3(0,-2.171) 4(0.5,-2.171) 5(1,-2.171) 6(1,2.171) 7(0.5,2.171) 8(0,2.171) 9(-0.5,2.171) 10(-1,2.171)
SO14-2
  rect 0.66x1.702 smd: 1(-3.81,-2.8) 2(-2.54,-2.8) 3(-1.27,-2.8) 4(0,-2.8) 5(1.27,-2.8) 6(2.54,-2.8) 7(3.81,-2.8) 8(3.81,2.8) 9(2.54,2.8) 10(1.27,2.8) 11(0,2.8) 12(-1.27,2.8) 13(-2.54,2.8) 14(-3.81,2.8)
SOD123F
  rect 1.194x1.194 smd: A(1.403,0) C(-1.403,0)
SOD323
  rect 1.27x0.889 smd: A(1.143,0) C(-1.143,0)
SON8
  rect 0.66x1.194 smd: 1(-1.92,-2.828) 2(-0.64,-2.828) 3(0.64,-2.828) 4(1.92,-2.828)
  custom 1.175x1.175 smd: 5(2,3.171)
  round 0.127 smd: 6(0.678,3.211) 7(-0.68,3.236) 8(-2.002,3.223)
SON8_FL
  round 0.127 smd: 1(-1.905,-3.071) 2(-0.635,-3.071) 6(0.635,2.931) 7(-0.635,2.931) 8(-1.905,2.931)
  custom 0.273x0.273 smd: 3(0.635,-3.071)
  rect 0.508x1.092 smd: 4(1.905,-2.779)
  custom 1.105x1.105 smd: 5(1.905,2.931)
SOT23
  rect 1.016x1.397 smd: 1(-0.94,-1.118) 2(0.94,-1.118) 3(0,1.118)
TPC50D30
  round 1.27 hole 0.762: 1(0,0)
TSSOP20_16P_PAD3_86X2_74_05-08-1924
  rect 0.381x1.27 smd: 1(-2.925,-2.81) 3(-1.625,-2.81) 5(-0.325,-2.81) 6(0.325,-2.81) 7(0.975,-2.81) 8(1.625,-2.81) 9(2.275,-2.81) 10(2.925,-2.81) 11(2.925,2.81) 12(2.275,2.81) 13(1.625,2.81) 14(0.975,2.81) 15(0.325,2.81) 16(-0.325,2.81) 18(-1.625,2.81) 20(-2.925,2.81)
  rect 3.861x2.743 smd: 21(0,0)
unnamed
  round 1.016 smd: (0,0)

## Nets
GND_POWER: C2.N(N2) C3.N(N2) C3_1.N(N2) C4.N(N2) C4_1.N(N2) C5.1 C6.1 C7.N(N2) C8.1 C9.1 C10.1 C11.1 C12.1 C13.1 C14.1 C16.1 C17.1 C18.1 C19.1 C20.1 C21.1 C22.N(N2) C22_1.N(N2) C23.N(N2) C23_1.N(N2) C26.N(N2) C27.N(N2) C27_1.N(N2) C28.N(N2) C28_1.N(N2) C29.1 C30.1 C31.N(N2) C32.1 C33.1 C34.1 C35.1 C36.1 C37.1 C38.1 C40.1 C41.1 C42.1 C43.1 C44.1 C45.1 C46.N(N2) C46_1.N(N2) C47.N(N2) C47_1.N(N2) C50.N(N2) C51.N(N2) C51_1.N(N2) C52.N(N2) C52_1.N(N2) C53.1 C54.1 C55.N(N2) C56.1 C57.1 C58.1 C59.1 C60.1 C61.1 C62.1 C64.1 C65.1 C66.1 C67.1 C68.1 C69.1 C70.N(N2) C70_1.N(N2) C71.N(N2) C71_1.N(N2) C74.N(N2) C75.N(N2) C75_1.N(N2) C76.N(N2) C76_1.N(N2) C77.1 C78.1 C79.N(N2) C80.1 C81.1 C82.1 C83.1 C84.1 C85.1 C86.1 C88.1 C89.1 C90.1 C91.1 C92.1 C93.1 C94.N(N2) C94_1.N(N2) C95.N(N2) C95_1.N(N2) C97.2(N2) C98.N(N2) C99.2(N2) C100.2(N2) C101.2(N2) C102.1 C103.2(N2) C106.2(N2) C107.2(N2) C108.2(N2) C109.1 C110.1 C111.1 C112.1 C113.1 C114.1 C115.1 C116.1 C117.2(N2) C118.2(N2) C119.2(N2) C122.2(N2) C123.2(N2) C124.2(N2) CC1.1 CC2.1 CC3.1 CC4.1 CC5.1 CC6.1 CC7.1 CC8.1 CFOUT1.2(N2) CFOUT2.2(N2) CFOUT3.2(N2) CFOUT4.2(N2) CGATE1.2(N2) CGATE2.2(N2) CGATE3.2(N2) CGATE4.2(N2) CIMON1.2(N2) CIMON2.2(N2) CIMON3.2(N2) CIMON4.2(N2) CP1.1 CP2.1 CP3.1 CP4.1 CP5.1 CP6.1 CP7.1 CP8.1 CSS1.1 CSS2.1 CSS3.1 CSS4.1 CVDD1.1 CVDD2.1 CVDD3.1 CVDD4.1 CXVCC1.1 CXVCC2.1 CXVCC3.1 CXVCC4.1 D2.1(P) D4.A(P) D9.A(P) E2.1(N1) E3.1(N1) GND1.1(N1) GND2.1(N1) GND3.1(N1) GND4.1(N1) JP1.3 JP2.3 MB1.1 MB1.2 MB1.3(S3) MB2.1 MB2.2 MB2.3(S3) MB3.1 MB3.2 MB3.3(S3) MB4.1 MB4.2 MB4.3(S3) MB5.1 MB5.2 MB5.3(S3) MB6.1 MB6.2 MB6.3(S3) MB7.1 MB7.2 MB7.3(S3) MB8.1 MB8.2 MB8.3(S3) MC1.1 MC1.2 MC1.3(S3) MC2.1 MC2.2 MC2.3(S3) MC3.1 MC3.2 MC3.3(S3) MC4.1 MC4.2 MC4.3(S3) MC5.1 MC5.2 MC5.3(S3) MC6.1 MC6.2 MC6.3(S3) MC7.1 MC7.2 MC7.3(S3) MC8.1 MC8.2 MC8.3(S3) P3.1(N1) P4.1(N1) P5.1(N1) P6.1(N1) R1B1.2(N2) R1B2.2(N2) R1B3.2(N2) R1B4.2(N2) R2B1.1 R2B2.1 R2B3.1 R2B4.1 R44.2(N2) R45.2(N2) R47.2(N2) R48.2(N2) R50.2(N2) R70.2(N2) R71.2(N2) R74.2(N2) R76.2(N2) R79.2(N2) REN2.1 REN4.1 REN6.1 REN8.1 RIMON1.2(N2) RIMON2.2(N2) RIMON3.2(N2) RIMON4.2(N2) RT1.1 RT2.1 RT3.1 RT4.1 RXVCC1.1 RXVCC2.1 RXVCC3.1 RXVCC4.1 U1.4 U1.22 U1.41 U2.4 U2.22 U2.41 U3.4 U3.22 U3.41 U4.4 U4.22 U4.41 U5.8 U6.7 U6.21 U7.7 U7.21 U8.5 U8.10 U8.11(V-) U8.12
VDD: C97.1 D1.C D3.C D5.C D7.C JP1.1 JP2.1 R41.1 R42.1 R43.1 RPWGD1.2(N2) RPWGD2.2(N2) RPWGD3.2(N2) RPWGD4.2(N2) U5.1(V+)
VIN: C1.2(N2) C25.2(N2) C49.2(N2) C73.2(N2) C99.1 C101.1 C117.1 E1.1(N1) L5.1 MDG1.1 MDG1.2 MDG1.3(S3) MDG2.1 MDG2.2 MDG2.3(S3) MDG3.1 MDG3.2 MDG3.3(S3) MDG4.1 MDG4.2 MDG4.3(S3) MDG5.1 MDG5.2 MDG5.3(S3) MDG6.1 MDG6.2 MDG6.3(S3) MDG7.1 MDG7.2 MDG7.3(S3) MDG8.1 MDG8.2 MDG8.3(S3) P1.1(N1) P2.1(N1) R69.1 R72.1 REN1.2(N2) REN3.2(N2) REN5.2(N2) REN7.2(N2) RIN1.2(N2) RIN2.2(N2) RIN3.2(N2) RIN4.2(N2) U7.1
BST1: CBST1.2(N2) DBST1.C RBST1.1
BST2: CBST2.1 DBST2.C RBST2.1
BST3: CBST3.2(N2) DBST3.C RBST3.1
BST4: CBST4.1 DBST4.C RBST4.1
BST5: CBST5.2(N2) DBST5.C RBST5.1
BST6: CBST6.1 DBST6.C RBST6.1
BST7: CBST7.2(N2) DBST7.C RBST7.1
BST8: CBST8.1 DBST8.C RBST8.1
EN: R77.2(N2) R80.1 R81.1 R82.1 R83.1 U8.1
EN1: R80.2(N2) REN1.1 REN2.2(N2) U1.37
EN2: R83.2(N2) REN3.1 REN4.2(N2) U2.37
EN3: R81.2(N2) REN5.1 REN6.2(N2) U3.37
EN4: R82.2(N2) REN7.1 REN8.2(N2) U4.37
EXTVCC_1: CXVCC1.2(N2) R5.2(N2) R51.2(N2) RXVCC1.2(N2) U1.25
EXTVCC_2: CXVCC2.2(N2) R15.2(N2) R52.2(N2) RXVCC2.2(N2) U2.25
EXTVCC_3: CXVCC3.2(N2) R25.2(N2) R53.2(N2) RXVCC3.2(N2) U3.25
EXTVCC_4: CXVCC4.2(N2) R35.2(N2) R54.2(N2) RXVCC4.2(N2) U4.25
FB1: R55.2(N2) R57.2(N2) R59.2(N2) R61.2(N2) R63.2(N2)
FB2: R56.2(N2) R58.2(N2) R60.2(N2) R62.2(N2) R64.2(N2)
IMON: IMON.1(N1) R8.1 R18.1 R28.1 R38.1
ISN1: C24.2(N2) R7.1 RSNPB1.1 U1.15
ISN2: C48.2(N2) R17.1 RSNPB2.1 U2.15
ISN3: C72.2(N2) R27.1 RSNPB3.1 U3.15
ISN4: C96.2(N2) R37.1 RSNPB4.1 U4.15
ISP1: C24.1 R6.1 RSNPA1.1 U1.16
ISP2: C48.1 R16.1 RSNPA2.1 U2.16
ISP3: C72.1 R26.1 RSNPA3.1 U3.16
ISP4: C96.1 R36.1 RSNPA4.1 U4.16
MODE1: JP1.2 JP1.4(S4) U1.40 U2.40 U3.40 U4.40
MODE2: JP2.2 JP2.4(S4) U1.39 U2.39 U3.39 U4.39
PWGD1: DS1.C U1.2
PWGD2: DS2.C U2.2
PWGD3: DS3.C U3.2
PWGD4: DS4.C U4.2
SYNC1: U1.1 U5.4
SYNC2: U2.1 U5.5
SYNC3: U3.1 U5.6
SYNC4: U4.1 U5.7
UNNAMED_2_ADLT82101_I27_BG1: RBG1.2(N2) U1.23
UNNAMED_2_ADLT82101_I27_BG2: RBG2.2(N2) U1.21
UNNAMED_2_ADLT82101_I27_BST1: RBST1.2(N2) U1.27
UNNAMED_2_ADLT82101_I27_BST2: RBST2.2(N2) U1.20
UNNAMED_2_ADLT82101_I27_DG: DG1.1(N1) R1.2(N2) U1.34
UNNAMED_2_ADLT82101_I27_FB1: R1A1.2(N2) R1B1.1 R3C1.1 U1.11
UNNAMED_2_ADLT82101_I27_FB2: R2A1.2(N2) R2B1.2(N2) R3C1.2(N2) U1.10
UNNAMED_2_ADLT82101_I27_GATEVCC: CGATE1.1 DBST1.A(P) DBST2.A(P) U1.24
UNNAMED_2_ADLT82101_I27_IMON: CIMON1.1 IMON1.1(N1) R8.2(N2) RIMON1.1 U1.7
UNNAMED_2_ADLT82101_I27_RT: RT1.2(N2) U1.3
UNNAMED_2_ADLT82101_I27_SNSN1: C15.2(N2) R4.2(N2) U1.30
UNNAMED_2_ADLT82101_I27_SNSP1: C15.1 R3.2(N2) U1.31
UNNAMED_2_ADLT82101_I27_SS: CSS1.2(N2) U1.6
UNNAMED_2_ADLT82101_I27_SW1: CBST1.1 MA1.1 MA1.2 MA1.3(S3) MA2.1 MA2.2 MA2.3(S3) MB1.5 MB1.6 MB1.7 MB1.8 MB2.5 MB2.6 MB2.7 MB2.8 RSNS1.4(N4) RSNS1_1.4(N4) U1.28
UNNAMED_2_ADLT82101_I27_SW2: CBST2.2(N2) L1.2(N2) L1B.1(N1) MC1.5 MC1.6 MC1.7 MC1.8 MC2.5 MC2.6 MC2.7 MC2.8 MD1.1 MD1.2 MD1.3(S3) MD2.1 MD2.2 MD2.3(S3) U1.19
UNNAMED_2_ADLT82101_I27_TG1: MA1.4 MA2.4 TPA1.1(N1) U1.29
UNNAMED_2_ADLT82101_I27_TG2: MD1.4 MD2.4 TPD1.1(N1) U1.18
UNNAMED_2_ADLT82101_I27_VC1: CP1.2(N2) R9.2(N2) RC1.2(N2) RC3.1 U1.8
UNNAMED_2_ADLT82101_I27_VC2: CP2.2(N2) R10.1 RC2.2(N2) RC3.2(N2) U1.9
UNNAMED_2_ADLT82101_I27_VDD: CVDD1.2(N2) D1.A(P) U1.5
UNNAMED_2_ADLT82101_I27_VIN: C5.2(N2) RIN1.1 U1.35
UNNAMED_2_ADLT82101_I27_VINP: C6.2(N2) R2.1 U1.33
UNNAMED_2_ADLT82101_I27_VOUT: CFOUT1.1 ROUT1.1 U1.13(VOUT)
UNNAMED_2_ADLTC6902_I7_MOD: R42.2(N2) R45.1 U5.9
UNNAMED_2_ADLTC6902_I7_PH: R43.2(N2) R44.1 U5.3
UNNAMED_2_ADLTC6902_I7_SET: R41.2(N2) U5.10
UNNAMED_2_CAP_I39_N1: C1.1 MDG1.4 MDG2.4 R1.1
UNNAMED_2_CAP_I149_N2: C16.2(N2) C17.2(N2) C18.2(N2) C19.2(N2) C20.2(N2) C21.2(N2) C22.P C22_1.P MD1.5 MD1.6 MD1.7 MD1.8 MD2.5 MD2.6 MD2.7 MD2.8 R6.2(N2) R65.1 ROUT1.2(N2) RSNS2.3 RSNS2.4(N4) RSNS2_1.3 RSNS2_1.4(N4)
UNNAMED_2_CAP_I184_N2: CC1.2(N2) RC1.1
UNNAMED_2_CAP_I185_N2: CC2.2(N2) RC2.1
UNNAMED_2_CAPP_I42_N1: C2.P C3.P C3_1.P C4.P C4_1.P C7.P C8.2(N2) C9.2(N2) C10.2(N2) C11.2(N2) C12.2(N2) C13.2(N2) C14.2(N2) MA1.5 MA1.6 MA1.7 MA1.8 MA2.5 MA2.6 MA2.7 MA2.8 MDG1.5 MDG1.6 MDG1.7 MDG1.8 MDG2.5 MDG2.6 MDG2.7 MDG2.8 R2.2(N2) RSNS3.2 RSNS3.4(N4) RSNS3_1.2 RSNS3_1.4(N4)
UNNAMED_2_DIOLED_I8_P: DS1.A(P) RPWGD1.1
UNNAMED_2_IND_I187_N1: L1.1 L1A.1(N1) RSNS1.2 RSNS1_1.2
UNNAMED_2_NCTESTPAD_I95_N1: MB1.4 MB2.4 RBG1.1 TPB1.1(N1)
UNNAMED_2_NCTESTPAD_I107_N1: MC1.4 MC2.4 RBG2.1 TPC1.1(N1)
UNNAMED_2_RES_I50_N2: RSNPA1.2(N2) RSNS3.3 RSNS3_1.3
UNNAMED_2_RES_I54_N2: RSNPB1.2(N2) RSNS3.1 RSNS3_1.1
UNNAMED_2_RES_I97_N1: R3.1 RSNS1.3 RSNS1_1.3
UNNAMED_2_RES_I103_N1: R4.1 RSNS1.1 RSNS1_1.1
UNNAMED_2_RES_I137_N1: R1A1.1 R1C1.1 R55.1
UNNAMED_2_RES_I140_N1: R2A1.1 R2C1.1 R56.1
UNNAMED_3_ADLT82101_I10_BG1: RBG5.2(N2) U3.23
UNNAMED_3_ADLT82101_I10_BG2: RBG6.2(N2) U3.21
UNNAMED_3_ADLT82101_I10_BST1: RBST5.2(N2) U3.27
UNNAMED_3_ADLT82101_I10_BST2: RBST6.2(N2) U3.20
UNNAMED_3_ADLT82101_I10_DG: DG3.1(N1) R21.2(N2) U3.34
UNNAMED_3_ADLT82101_I10_FB1: R1A3.2(N2) R1B3.1 R3C3.1 U3.11
UNNAMED_3_ADLT82101_I10_FB2: R2A3.2(N2) R2B3.2(N2) R3C3.2(N2) U3.10
UNNAMED_3_ADLT82101_I10_GATEVCC: CGATE3.1 DBST5.A(P) DBST6.A(P) U3.24
